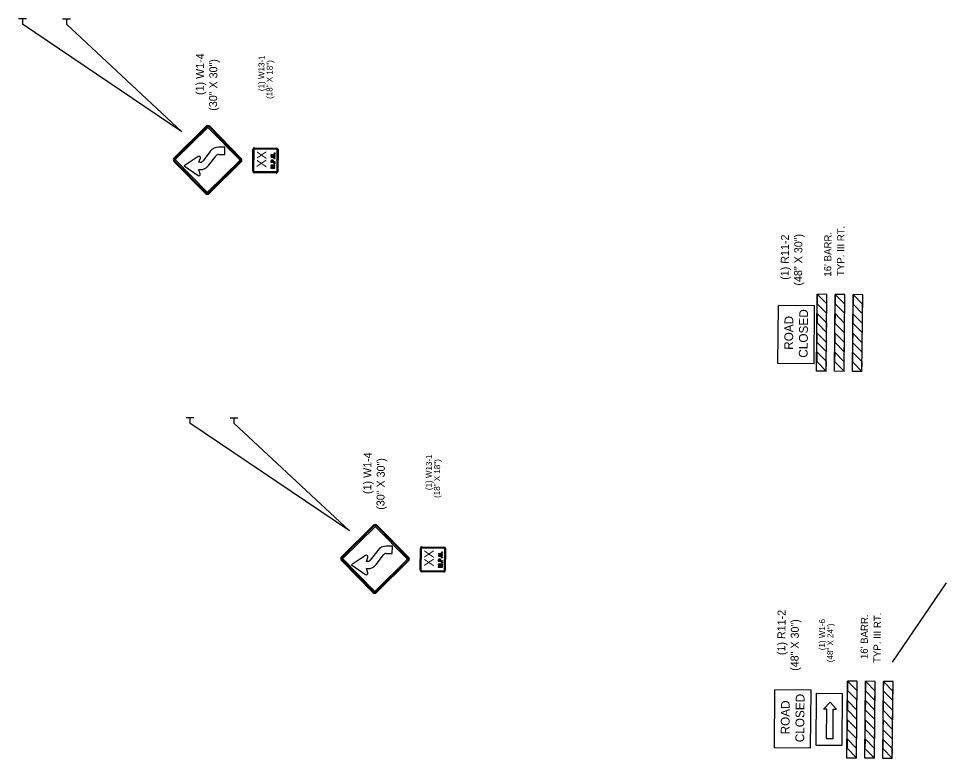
# Model space of a CAD drawing. Extents: x 1770269 to 1771406, y 724066 to 730989.
# Drawn here: x 1770374 to 1771301, y 728416 to 729156 of the extents above; entities that cross this region are included whole.
import ezdxf

# ---------------------------------------------------------------- set-up
doc = ezdxf.new("R2010")
doc.units = 0
for name, color, linetype in [('Default', 7, 'Continuous'), ('R_Border PE', 7, 'Continuous'), ('R_MOT', 7, 'Continuous'), ('Roadway-Signs', 7, 'Continuous')]:
    doc.layers.add(name, color=color, linetype=linetype)

msp = doc.modelspace()

# ---------------------------------------------------------------- linework, layer by layer
at = {"layer": 'Default'}
for p, q in [((1770373.86, 729155.68), (1770381.69, 729155.64)), ((1770377.75, 729155.55), (1770377.73, 729150.21)), ((1770417.86, 729155.47), (1770425.69, 729155.43)), ((1770421.75, 729155.34), (1770421.73, 729150)), ((1770541.23, 728756.8), (1770549.05, 728756.76)), ((1770545.12, 728756.67), (1770545.09, 728751.32)), ((1770585.23, 728756.59), (1770593.05, 728756.55)), ((1770589.12, 728756.46), (1770589.09, 728751.11))]:
    msp.add_line(p, q, dxfattribs=at)
at = {"layer": 'R_Border PE'}
for p, q in [((1770537.2, 729042.36), (1770377.73, 729150.21)), ((1770537.2, 729042.36), (1770421.73, 729150)), ((1770704.56, 728643.48), (1770545.09, 728751.32)), ((1770704.56, 728643.48), (1770589.09, 728751.11)), ((1771247.41, 728512.37), (1771301.26, 728591.59))]:
    msp.add_line(p, q, dxfattribs=at)
at = {"layer": 'R_MOT'}
for p, q in [((1771171.51, 728803.19), (1771172.2, 728880.06)), ((1771181.86, 728879.98), (1771172.2, 728880.06)), ((1771181.16, 728803.1), (1771181.86, 728879.98)), ((1771181.83, 728879.92), (1771181.77, 728879.98)), ((1771189.4, 728803.03), (1771190.1, 728879.9)), ((1771199.72, 728879.81), (1771190.1, 728879.9)), ((1771199.72, 728879.81), (1771190.1, 728879.9)), ((1771199.02, 728802.94), (1771199.72, 728879.81)), ((1771207.24, 728802.86), (1771207.93, 728879.74)), ((1771217.56, 728879.65), (1771207.93, 728879.74)), ((1771216.86, 728802.78), (1771217.56, 728879.65)), ((1771132.82, 728811), (1771133.34, 728868.96)), ((1771169.55, 728868.63), (1771133.34, 728868.96)), ((1771169.02, 728810.67), (1771169.55, 728868.63)), ((1771169.02, 728810.67), (1771132.82, 728811)), ((1771181.16, 728803.1), (1771171.51, 728803.19)), ((1771199.02, 728802.94), (1771189.4, 728803.03)), ((1771216.86, 728802.78), (1771207.24, 728802.86)), ((1771201.8, 728416.43), (1771202.5, 728493.31)), ((1771212.15, 728493.22), (1771202.5, 728493.31)), ((1771211.45, 728416.34), (1771212.15, 728493.22)), ((1771212.12, 728493.16), (1771212.06, 728493.22)), ((1771219.69, 728416.27), (1771220.39, 728493.14)), ((1771230.01, 728493.06), (1771220.39, 728493.14)), ((1771230.01, 728493.06), (1771220.39, 728493.14)), ((1771229.31, 728416.18), (1771230.01, 728493.06)), ((1771237.53, 728416.11), (1771238.22, 728492.98)), ((1771247.85, 728492.89), (1771238.22, 728492.98)), ((1771247.15, 728416.02), (1771247.85, 728492.89)), ((1771129.32, 728426.55), (1771129.85, 728484.51)), ((1771166.06, 728484.18), (1771129.85, 728484.51)), ((1771165.53, 728426.22), (1771166.06, 728484.18)), ((1771178.38, 728465.28), (1771184.99, 728472.39)), ((1771184.99, 728472.39), (1771191.47, 728465.16)), ((1771181.65, 728465.25), (1771178.38, 728465.28)), ((1771181.39, 728435.86), (1771181.65, 728465.25)), ((1771187.93, 728435.8), (1771188.2, 728465.19)), ((1771188.2, 728465.19), (1771191.47, 728465.16)), ((1771181.39, 728435.86), (1771187.93, 728435.8)), ((1771165.53, 728426.22), (1771129.32, 728426.55)), ((1771211.45, 728416.34), (1771201.8, 728416.43)), ((1771229.31, 728416.18), (1771219.69, 728416.27)), ((1771247.15, 728416.02), (1771237.53, 728416.11))]:
    msp.add_line(p, q, dxfattribs=at)
for points in [[(1771172.2, 728880.06), (1771172.15, 728870.61), (1771181.66, 728860.93), (1771181.74, 728870.35)], [(1771190.1, 728879.9), (1771190.04, 728870.45), (1771199.55, 728860.77), (1771199.63, 728870.19)], [(1771207.93, 728879.74), (1771207.88, 728870.29), (1771217.38, 728860.61), (1771217.47, 728870.03)], [(1771172.03, 728860.85), (1771171.97, 728851.4), (1771181.48, 728841.72), (1771181.57, 728851.14)], [(1771189.92, 728860.69), (1771189.87, 728851.24), (1771199.37, 728841.56), (1771199.46, 728850.98)], [(1771207.76, 728860.53), (1771207.7, 728851.08), (1771217.21, 728841.4), (1771217.29, 728850.82)], [(1771171.86, 728841.65), (1771171.8, 728832.19), (1771181.31, 728822.51), (1771181.39, 728831.93)], [(1771189.75, 728841.48), (1771189.69, 728832.03), (1771199.2, 728822.35), (1771199.29, 728831.77)], [(1771207.58, 728841.32), (1771207.53, 728831.87), (1771217.03, 728822.19), (1771217.12, 728831.61)], [(1771171.68, 728822.44), (1771171.62, 728812.99), (1771181.13, 728803.3), (1771181.22, 728812.73)], [(1771189.57, 728822.27), (1771189.52, 728812.82), (1771199.03, 728803.14), (1771199.11, 728812.56)], [(1771207.41, 728822.11), (1771207.35, 728812.66), (1771216.86, 728802.98), (1771216.95, 728812.4)], [(1771202.5, 728493.31), (1771202.44, 728483.85), (1771211.95, 728474.17), (1771212.03, 728483.59)], [(1771220.39, 728493.14), (1771220.33, 728483.69), (1771229.84, 728474.01), (1771229.93, 728483.43)], [(1771238.22, 728492.98), (1771238.17, 728483.53), (1771247.68, 728473.85), (1771247.76, 728483.27)], [(1771171.03, 728480.92), (1771170.56, 728429.39), (1771196.91, 728429.15), (1771197.38, 728480.68)], [(1771202.32, 728474.1), (1771202.26, 728464.65), (1771211.77, 728454.96), (1771211.86, 728464.39)], [(1771220.21, 728473.93), (1771220.16, 728464.48), (1771229.67, 728454.8), (1771229.75, 728464.22)], [(1771238.05, 728473.77), (1771237.99, 728464.32), (1771247.5, 728454.64), (1771247.59, 728464.06)], [(1771202.15, 728454.89), (1771202.09, 728445.44), (1771211.6, 728435.75), (1771211.68, 728445.18)], [(1771220.04, 728454.73), (1771219.98, 728445.27), (1771229.49, 728435.59), (1771229.58, 728445.01)], [(1771237.88, 728454.56), (1771237.82, 728445.11), (1771247.33, 728435.43), (1771247.41, 728444.85)], [(1771201.97, 728435.68), (1771201.92, 728426.23), (1771211.42, 728416.55), (1771211.51, 728425.97)], [(1771219.87, 728435.52), (1771219.81, 728426.07), (1771229.32, 728416.38), (1771229.4, 728425.81)], [(1771237.7, 728435.35), (1771237.64, 728425.9), (1771247.15, 728416.22), (1771247.24, 728425.64)]]:
    msp.add_lwpolyline(points, close=True, dxfattribs=at)
at = {"layer": 'Roadway-Signs'}
for p, q in [((1770529.26, 729016.44), (1770561.36, 729047.97)), ((1770529.84, 729015.85), (1770561.95, 729047.37)), ((1770564.3, 729047.35), (1770595.83, 729015.25)), ((1770564.9, 729047.94), (1770596.43, 729015.83)), ((1770530.72, 729014.95), (1770562.82, 729046.48)), ((1770563.41, 729046.48), (1770594.94, 729014.37)), ((1770565.51, 729022.94), (1770558.02, 729013.16)), ((1770573.81, 729019.74), (1770580.06, 729019.68)), ((1770580.13, 729026.97), (1770573.88, 729027.03)), ((1770580.06, 729019.68), (1770580.13, 729026.97)), ((1770607.98, 729003.02), (1770608.18, 729024.89)), ((1770608.37, 729003.02), (1770608.57, 729024.89)), ((1770609.02, 729003.01), (1770609.22, 729024.88)), ((1770609.75, 729026.05), (1770631.63, 729025.85)), ((1770609.75, 729025.4), (1770631.62, 729025.2)), ((1770609.76, 729026.44), (1770631.63, 729026.24)), ((1770632.14, 729024.68), (1770631.94, 729002.8)), ((1770632.79, 729024.67), (1770632.59, 729002.8)), ((1770633.18, 729024.67), (1770632.98, 729002.79)), ((1770560.75, 728980.8), (1770529.22, 729012.9)), ((1770561.35, 728981.38), (1770529.82, 729013.49)), ((1770562.24, 728982.26), (1770530.71, 729014.36)), ((1770553.39, 729017.84), (1770539.33, 729008.43)), ((1770554.18, 729011.95), (1770555.58, 729016.17)), ((1770555.51, 729011.93), (1770554.18, 729011.95)), ((1770562.83, 729014.37), (1770562.83, 729014.37)), ((1770594.94, 729013.78), (1770562.83, 728982.25)), ((1770595.81, 729012.89), (1770563.71, 728981.36)), ((1770563.81, 729008.73), (1770571.3, 729018.51)), ((1770596.4, 729012.29), (1770564.29, 728980.77)), ((1770539.33, 729008.43), (1770553.22, 728998.77)), ((1770555.44, 729000.4), (1770554.12, 729004.65)), ((1770554.12, 729004.65), (1770555.45, 729004.64)), ((1770631.41, 729001.63), (1770609.53, 729001.83)), ((1770631.4, 729001.24), (1770609.53, 729001.44)), ((1770631.41, 729002.29), (1770609.54, 729002.48)), ((1770696.62, 728617.56), (1770728.73, 728649.09)), ((1770697.2, 728616.96), (1770729.31, 728648.49)), ((1770731.67, 728648.47), (1770763.2, 728616.36)), ((1770732.26, 728649.05), (1770763.79, 728616.95)), ((1770698.08, 728616.07), (1770730.19, 728647.6)), ((1770730.78, 728647.6), (1770762.3, 728615.49)), ((1770732.88, 728624.06), (1770725.38, 728614.28)), ((1770741.17, 728620.85), (1770747.42, 728620.8)), ((1770747.49, 728628.09), (1770741.24, 728628.15)), ((1770747.42, 728620.8), (1770747.49, 728628.09)), ((1770775.34, 728604.14), (1770775.54, 728626.01)), ((1770775.74, 728604.13), (1770775.93, 728626.01)), ((1770776.39, 728604.13), (1770776.59, 728626)), ((1770777.11, 728626.52), (1770798.98, 728626.32)), ((1770777.12, 728627.56), (1770798.99, 728627.36)), ((1770777.12, 728627.17), (1770798.99, 728626.97)), ((1770799.5, 728625.79), (1770799.3, 728603.92)), ((1770800.15, 728625.79), (1770799.95, 728603.91)), ((1770800.54, 728625.78), (1770800.34, 728603.91)), ((1770728.12, 728581.92), (1770696.59, 728614.02)), ((1770728.71, 728582.5), (1770697.18, 728614.61)), ((1770729.6, 728583.37), (1770698.07, 728615.48)), ((1770720.75, 728618.96), (1770706.7, 728609.55)), ((1770721.55, 728613.06), (1770722.95, 728617.29)), ((1770722.87, 728613.05), (1770721.55, 728613.06)), ((1770730.19, 728615.49), (1770730.19, 728615.49)), ((1770762.3, 728614.9), (1770730.19, 728583.37)), ((1770763.18, 728614.01), (1770731.07, 728582.48)), ((1770731.17, 728609.84), (1770738.67, 728619.63)), ((1770763.76, 728613.41), (1770731.65, 728581.88)), ((1770706.7, 728609.55), (1770720.58, 728599.89)), ((1770722.8, 728601.52), (1770721.48, 728605.77)), ((1770721.48, 728605.77), (1770722.81, 728605.76)), ((1770798.77, 728602.36), (1770776.89, 728602.56)), ((1770798.78, 728603.4), (1770776.9, 728603.6)), ((1770798.77, 728602.75), (1770776.9, 728602.95))]:
    msp.add_line(p, q, dxfattribs=at)
for points in [[(1770626.08, 729017.07), (1770630.25, 729017.03), (1770630.25, 729017.65), (1770628.41, 729017.66), (1770628.42, 729018.79), (1770630.26, 729018.77), (1770630.27, 729019.39), (1770626.1, 729019.43), (1770626.1, 729018.81), (1770627.7, 729018.8), (1770627.69, 729017.67), (1770626.09, 729017.69), (1770626.08, 729017.07)], [(1770630.12, 729020.8), (1770630.08, 729020.77), (1770630.05, 729020.75), (1770630.02, 729020.73), (1770629.92, 729020.7), (1770629.85, 729020.71), (1770629.79, 729020.71), (1770629.72, 729020.71), (1770629.62, 729020.73), (1770629.56, 729020.75), (1770629.46, 729020.8), (1770629.43, 729020.82), (1770629.39, 729020.85), (1770629.36, 729020.89), (1770629.33, 729020.94), (1770629.3, 729021.03), (1770629.33, 729021.12), (1770629.37, 729021.19), (1770629.43, 729021.24), (1770629.53, 729021.31), (1770629.6, 729021.33), (1770629.76, 729021.35), (1770629.83, 729021.35), (1770629.96, 729021.33), (1770630.09, 729021.28), (1770630.19, 729021.23), (1770630.25, 729021.16), (1770630.28, 729021.12), (1770630.28, 729021.05), (1770630.28, 729020.98), (1770630.25, 729020.91), (1770630.18, 729020.84), (1770630.12, 729020.8)], [(1770626.04, 729013.23), (1770626.03, 729011.97), (1770630.2, 729011.93), (1770630.21, 729012.55), (1770628.73, 729012.56), (1770628.73, 729013.21)], [(1770628.73, 729013.21), (1770628.7, 729013.34), (1770628.67, 729013.44), (1770628.64, 729013.5), (1770628.61, 729013.57), (1770628.57, 729013.62), (1770628.54, 729013.67), (1770628.48, 729013.74), (1770628.41, 729013.81), (1770628.35, 729013.85), (1770628.28, 729013.9), (1770628.22, 729013.94), (1770628.12, 729013.99), (1770628.02, 729014.04), (1770627.95, 729014.06), (1770627.89, 729014.09), (1770627.79, 729014.11), (1770627.69, 729014.13), (1770627.53, 729014.16), (1770627.43, 729014.16), (1770627.3, 729014.16), (1770627.14, 729014.14), (1770627.1, 729014.14), (1770627, 729014.12), (1770626.9, 729014.1), (1770626.77, 729014.05), (1770626.67, 729014), (1770626.58, 729013.96), (1770626.51, 729013.91), (1770626.44, 729013.87), (1770626.38, 729013.82), (1770626.31, 729013.76), (1770626.25, 729013.69), (1770626.21, 729013.64), (1770626.18, 729013.6), (1770626.15, 729013.53), (1770626.11, 729013.48), (1770626.08, 729013.37), (1770626.04, 729013.23)], [(1770628.01, 729013.07), (1770628.01, 729013.12), (1770627.98, 729013.21), (1770627.95, 729013.28), (1770627.92, 729013.33), (1770627.85, 729013.4), (1770627.79, 729013.44), (1770627.75, 729013.47), (1770627.65, 729013.51), (1770627.56, 729013.54), (1770627.42, 729013.56), (1770627.36, 729013.56), (1770627.2, 729013.54), (1770627.1, 729013.52), (1770627, 729013.47), (1770626.93, 729013.43), (1770626.87, 729013.38), (1770626.83, 729013.34), (1770626.8, 729013.29), (1770626.77, 729013.25), (1770626.73, 729013.13), (1770626.73, 729013.11), (1770626.73, 729013.09)], [(1770626.73, 729013.09), (1770626.73, 729012.58), (1770628.01, 729012.57), (1770628.01, 729013.07)], [(1770630.02, 729010.44), (1770629.99, 729010.42), (1770629.96, 729010.39), (1770629.92, 729010.37), (1770629.82, 729010.35), (1770629.76, 729010.35), (1770629.69, 729010.35), (1770629.63, 729010.35), (1770629.53, 729010.37), (1770629.46, 729010.4), (1770629.37, 729010.44), (1770629.33, 729010.47), (1770629.3, 729010.49), (1770629.27, 729010.54), (1770629.24, 729010.58), (1770629.2, 729010.68), (1770629.24, 729010.77), (1770629.27, 729010.84), (1770629.34, 729010.88), (1770629.44, 729010.95), (1770629.5, 729010.97), (1770629.67, 729010.99), (1770629.73, 729010.99), (1770629.86, 729010.97), (1770629.99, 729010.92), (1770630.09, 729010.87), (1770630.16, 729010.8), (1770630.19, 729010.76), (1770630.19, 729010.69), (1770630.19, 729010.62), (1770630.15, 729010.55), (1770630.09, 729010.48), (1770630.02, 729010.44)], [(1770630.07, 729015.54), (1770630.04, 729015.51), (1770630, 729015.49), (1770629.97, 729015.47), (1770629.87, 729015.45), (1770629.8, 729015.45), (1770629.74, 729015.45), (1770629.67, 729015.45), (1770629.58, 729015.47), (1770629.51, 729015.5), (1770629.41, 729015.54), (1770629.38, 729015.57), (1770629.35, 729015.59), (1770629.31, 729015.64), (1770629.28, 729015.68), (1770629.25, 729015.77), (1770629.28, 729015.86), (1770629.32, 729015.93), (1770629.38, 729015.98), (1770629.48, 729016.05), (1770629.55, 729016.07), (1770629.71, 729016.09), (1770629.78, 729016.09), (1770629.91, 729016.07), (1770630.04, 729016.02), (1770630.14, 729015.97), (1770630.2, 729015.9), (1770630.24, 729015.86), (1770630.23, 729015.79), (1770630.23, 729015.72), (1770630.2, 729015.65), (1770630.13, 729015.58), (1770630.07, 729015.54)], [(1770630.25, 729017.03), (1770630.25, 729017.65)], [(1770625.98, 729006.18), (1770630.15, 729006.14), (1770630.15, 729006.72), (1770627.26, 729006.74), (1770627, 729006.72), (1770627.2, 729006.77), (1770630.16, 729007.31), (1770630.16, 729007.91), (1770627.22, 729008.51), (1770627.02, 729008.56), (1770627.28, 729008.53), (1770630.17, 729008.51), (1770630.17, 729009.08), (1770626.01, 729009.12), (1770626, 729008.25), (1770628.82, 729007.67), (1770629.18, 729007.62), (1770628.81, 729007.58), (1770625.99, 729007.05), (1770625.98, 729006.18)], [(1770797.48, 728621.91), (1770797.45, 728621.89), (1770797.41, 728621.87), (1770797.38, 728621.85), (1770797.28, 728621.82), (1770797.21, 728621.82), (1770797.15, 728621.82), (1770797.08, 728621.82), (1770796.99, 728621.85), (1770796.92, 728621.87), (1770796.82, 728621.92), (1770796.79, 728621.94), (1770796.76, 728621.97), (1770796.72, 728622.01), (1770796.69, 728622.06), (1770796.66, 728622.15), (1770796.69, 728622.24), (1770796.73, 728622.31), (1770796.79, 728622.36), (1770796.89, 728622.42), (1770796.96, 728622.45), (1770797.12, 728622.47), (1770797.19, 728622.47), (1770797.32, 728622.44), (1770797.45, 728622.4), (1770797.55, 728622.35), (1770797.61, 728622.28), (1770797.65, 728622.23), (1770797.64, 728622.16), (1770797.64, 728622.1), (1770797.61, 728622.03), (1770797.54, 728621.96), (1770797.48, 728621.91)], [(1770793.41, 728614.35), (1770793.4, 728613.09), (1770797.56, 728613.05), (1770797.57, 728613.67), (1770796.09, 728613.68), (1770796.1, 728614.32)], [(1770796.1, 728614.32), (1770796.07, 728614.46), (1770796.03, 728614.55), (1770796, 728614.62), (1770795.97, 728614.69), (1770795.94, 728614.74), (1770795.9, 728614.79), (1770795.84, 728614.85), (1770795.77, 728614.92), (1770795.71, 728614.97), (1770795.64, 728615.02), (1770795.58, 728615.06), (1770795.48, 728615.11), (1770795.38, 728615.16), (1770795.32, 728615.18), (1770795.25, 728615.2), (1770795.15, 728615.23), (1770795.06, 728615.25), (1770794.89, 728615.28), (1770794.79, 728615.28), (1770794.66, 728615.28), (1770794.5, 728615.26), (1770794.46, 728615.26), (1770794.37, 728615.24), (1770794.27, 728615.21), (1770794.14, 728615.17), (1770794.04, 728615.12), (1770793.94, 728615.08), (1770793.87, 728615.03), (1770793.81, 728614.99), (1770793.74, 728614.94), (1770793.67, 728614.87), (1770793.61, 728614.81), (1770793.57, 728614.76), (1770793.54, 728614.72), (1770793.51, 728614.65), (1770793.48, 728614.6), (1770793.44, 728614.49), (1770793.41, 728614.35)], [(1770793.44, 728618.18), (1770797.61, 728618.15), (1770797.61, 728618.77), (1770795.78, 728618.78), (1770795.79, 728619.91), (1770797.62, 728619.89), (1770797.63, 728620.51), (1770793.46, 728620.55), (1770793.46, 728619.93), (1770795.07, 728619.91), (1770795.05, 728618.79), (1770793.45, 728618.8), (1770793.44, 728618.18)], [(1770795.37, 728614.19), (1770795.37, 728614.24), (1770795.34, 728614.33), (1770795.31, 728614.4), (1770795.28, 728614.45), (1770795.21, 728614.52), (1770795.15, 728614.56), (1770795.11, 728614.59), (1770795.02, 728614.63), (1770794.92, 728614.66), (1770794.79, 728614.68), (1770794.72, 728614.68), (1770794.56, 728614.66), (1770794.46, 728614.64), (1770794.36, 728614.59), (1770794.29, 728614.55), (1770794.23, 728614.5), (1770794.2, 728614.46), (1770794.16, 728614.41), (1770794.13, 728614.36), (1770794.09, 728614.25), (1770794.09, 728614.23), (1770794.09, 728614.2)], [(1770794.09, 728614.2), (1770794.09, 728613.7), (1770795.37, 728613.69), (1770795.37, 728614.19)], [(1770797.38, 728611.56), (1770797.35, 728611.53), (1770797.32, 728611.51), (1770797.29, 728611.49), (1770797.19, 728611.47), (1770797.12, 728611.47), (1770797.06, 728611.47), (1770796.99, 728611.47), (1770796.89, 728611.49), (1770796.83, 728611.52), (1770796.73, 728611.56), (1770796.7, 728611.59), (1770796.66, 728611.61), (1770796.63, 728611.65), (1770796.6, 728611.7), (1770796.57, 728611.79), (1770796.6, 728611.89), (1770796.63, 728611.95), (1770796.7, 728612), (1770796.8, 728612.07), (1770796.86, 728612.09), (1770797.03, 728612.11), (1770797.09, 728612.11), (1770797.23, 728612.09), (1770797.36, 728612.04), (1770797.45, 728611.99), (1770797.52, 728611.92), (1770797.55, 728611.88), (1770797.55, 728611.81), (1770797.55, 728611.74), (1770797.52, 728611.67), (1770797.45, 728611.6), (1770797.38, 728611.56)], [(1770797.43, 728616.65), (1770797.4, 728616.63), (1770797.36, 728616.61), (1770797.33, 728616.59), (1770797.23, 728616.56), (1770797.17, 728616.56), (1770797.1, 728616.57), (1770797.04, 728616.57), (1770796.94, 728616.59), (1770796.87, 728616.61), (1770796.77, 728616.66), (1770796.74, 728616.68), (1770796.71, 728616.71), (1770796.68, 728616.75), (1770796.64, 728616.8), (1770796.61, 728616.89), (1770796.65, 728616.98), (1770796.68, 728617.05), (1770796.75, 728617.1), (1770796.84, 728617.17), (1770796.91, 728617.19), (1770797.07, 728617.21), (1770797.14, 728617.21), (1770797.27, 728617.18), (1770797.4, 728617.14), (1770797.5, 728617.09), (1770797.56, 728617.02), (1770797.6, 728616.97), (1770797.6, 728616.91), (1770797.6, 728616.84), (1770797.56, 728616.77), (1770797.5, 728616.7), (1770797.43, 728616.65)], [(1770797.61, 728618.15), (1770797.61, 728618.77)], [(1770793.34, 728607.3), (1770797.51, 728607.26), (1770797.51, 728607.83), (1770794.63, 728607.86), (1770794.36, 728607.84), (1770794.56, 728607.88), (1770797.52, 728608.43), (1770797.53, 728609.03), (1770794.58, 728609.63), (1770794.38, 728609.68), (1770794.64, 728609.65), (1770797.53, 728609.63), (1770797.54, 728610.2), (1770793.37, 728610.24), (1770793.36, 728609.37), (1770796.18, 728608.79), (1770796.54, 728608.74), (1770796.18, 728608.7), (1770793.35, 728608.17), (1770793.34, 728607.3)]]:
    msp.add_lwpolyline(points, dxfattribs=at)
for centre, radius, start, end in [((1770563.12, 729046.19), 2.5, 44.47959, 134.47959), ((1770563.12, 729046.19), 1.67, 44.47959, 134.47959), ((1770563.12, 729046.19), 0.417, 44.47959, 134.47959), ((1770573.78, 729016.61), 10.42, 89.47959, 142.56152), ((1770573.78, 729016.61), 3.13, 89.47959, 142.56152), ((1770609.74, 729024.88), 1.56, 89.47959, 179.47959), ((1770609.74, 729024.88), 1.17, 89.47959, 179.47959), ((1770609.74, 729024.88), 0.521, 89.47959, 179.47959), ((1770631.62, 729024.68), 0.521, 359.47959, 89.47959), ((1770631.62, 729024.68), 1.56, 359.47959, 89.47959), ((1770631.62, 729024.68), 1.17, 359.47959, 89.47959), ((1770531.01, 729014.66), 2.5, 134.47959, 224.47959), ((1770531.01, 729014.66), 1.67, 134.47959, 224.47959), ((1770531.01, 729014.66), 0.417, 134.47959, 224.47959), ((1770554.2, 729016.63), 1.46, 341.66714, 123.80356), ((1770555.54, 729015.06), 3.13, 269.47959, 322.56114), ((1770594.64, 729014.08), 0.417, 314.47959, 44.47959), ((1770594.64, 729014.08), 1.67, 314.47959, 44.47959), ((1770594.64, 729014.08), 2.5, 314.47959, 44.47959), ((1770555.54, 729015.06), 10.42, 269.47959, 322.56152), ((1770609.54, 729003.01), 1.56, 179.47959, 269.47959), ((1770609.54, 729003.01), 1.17, 179.47959, 269.47959), ((1770609.54, 729003.01), 0.521, 179.47959, 269.47959), ((1770631.42, 729002.81), 1.56, 269.47959, 359.47959), ((1770631.42, 729002.81), 1.17, 269.47959, 359.47959), ((1770631.42, 729002.81), 0.521, 269.47959, 359.47959), ((1770554.05, 728999.97), 1.46, 235.15563, 17.29204), ((1770562.54, 728982.55), 2.5, 224.47959, 314.47959), ((1770562.54, 728982.55), 1.67, 224.47959, 314.47959), ((1770562.54, 728982.55), 0.417, 224.47959, 314.47959), ((1770730.48, 728647.3), 2.5, 44.47959, 134.47959), ((1770730.48, 728647.3), 1.67, 44.47959, 134.47959), ((1770730.48, 728647.3), 0.417, 44.47959, 134.47959), ((1770741.15, 728617.73), 10.42, 89.47959, 142.56152), ((1770741.15, 728617.73), 3.13, 89.47959, 142.56152), ((1770777.11, 728626), 1.56, 89.47959, 179.47959), ((1770777.11, 728626), 1.17, 89.47959, 179.47959), ((1770777.11, 728626), 0.521, 89.47959, 179.47959), ((1770798.98, 728625.8), 0.521, 359.47959, 89.47959), ((1770798.98, 728625.8), 1.56, 359.47959, 89.47959), ((1770798.98, 728625.8), 1.17, 359.47959, 89.47959), ((1770698.37, 728615.77), 2.5, 134.47959, 224.47959), ((1770698.37, 728615.77), 1.67, 134.47959, 224.47959), ((1770698.37, 728615.77), 0.417, 134.47959, 224.47959), ((1770721.56, 728617.75), 1.46, 341.66714, 123.80356), ((1770722.9, 728616.18), 3.13, 269.47959, 322.56114), ((1770762.01, 728615.2), 0.417, 314.47959, 44.47959), ((1770762.01, 728615.2), 1.67, 314.47959, 44.47959), ((1770762.01, 728615.2), 2.5, 314.47959, 44.47959), ((1770722.9, 728616.18), 10.42, 269.47959, 322.56152), ((1770776.91, 728604.12), 1.56, 179.47959, 269.47959), ((1770776.91, 728604.12), 1.17, 179.47959, 269.47959), ((1770776.91, 728604.12), 0.521, 179.47959, 269.47959), ((1770798.78, 728603.92), 1.56, 269.47959, 359.47959), ((1770798.78, 728603.92), 1.17, 269.47959, 359.47959), ((1770798.78, 728603.92), 0.521, 269.47959, 359.47959), ((1770721.41, 728601.08), 1.46, 235.15563, 17.29204), ((1770729.9, 728583.67), 2.5, 224.47959, 314.47959), ((1770729.9, 728583.67), 1.67, 224.47959, 314.47959), ((1770729.9, 728583.67), 0.417, 224.47959, 314.47959)]:
    msp.add_arc(centre, radius, start, end, dxfattribs=at)

# ---------------------------------------------------------------- texts
at = {"layer": 'R_MOT'}
for s, height, p in [('(1) W1-4', 8.004, (1770558.97, 729079.23)), ('(30" X 30")', 8.004, (1770572.21, 729063.48)), ('(1) W13-1', 6, (1770619.38, 729083.1)), ('(18" X 18")', 6, (1770627.56, 729075.32)), ('TYP. III RT.', 7.2036, (1771198.97, 728898.27)), ('(1) R11-2', 8.004, (1771143.54, 728894.5)), ('(48" X 30")', 8.004, (1771156.87, 728888.71)), ("16' BARR.", 7.204, (1771186.1, 728897.67)), ('CLOSED', 8.817, (1771162.54, 728816.58)), ('ROAD', 8.774, (1771147.91, 728824.5)), ('(1) W1-4', 8.004, (1770726.33, 728680.35)), ('(30" X 30")', 8.004, (1770739.57, 728664.6)), ('(1) W13-1', 6, (1770786.74, 728684.22)), ('(18" X 18")', 6, (1770794.92, 728676.44)), ('(1) R11-2', 8.004, (1771140.13, 728519.31)), ("16' BARR.", 7.204, (1771222.57, 728515.31)), ('TYP. III RT.', 7.2036, (1771235.41, 728511.45)), ('(48" X 30")', 8.004, (1771153.37, 728503.56)), ('(1) W1-6', 6, (1771179.75, 728524.19)), ('(48" X 24")', 6, (1771187.9, 728512.19)), ('ROAD', 8.774, (1771144.42, 728440.04)), ('CLOSED', 8.817, (1771159.04, 728432.13))]:
    msp.add_text(s, height=height, rotation=89.47959, dxfattribs=at).set_placement(p)
at = {"layer": 'Roadway-Signs'}
for p in [(1770621.37, 729006.63), (1770788.73, 728607.75)]:
    msp.add_text('XX', height=9.375, rotation=89.47959, dxfattribs=at).set_placement(p)

doc.saveas('drawing.dxf')
